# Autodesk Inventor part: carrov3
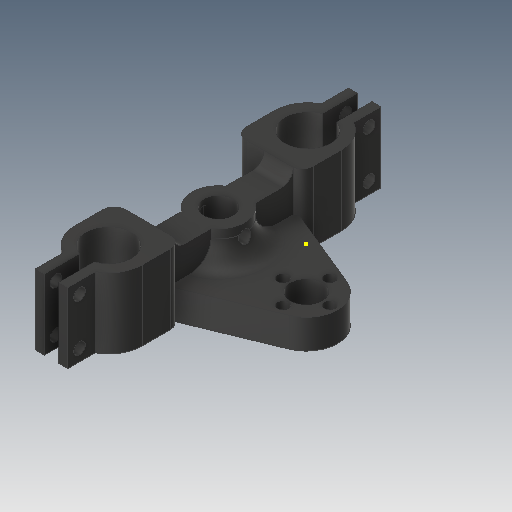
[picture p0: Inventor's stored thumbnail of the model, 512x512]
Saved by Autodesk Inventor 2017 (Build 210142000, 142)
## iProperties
Created: 2018-08
Part Number: carrov3
Material: Plastic, Opaque Black
Document SubType Name: Modeling
Designer: JK
Density: 0.952 g/cm^3
Appearance: Smooth - Black
Author: JK
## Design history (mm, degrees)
sketch "Sketch1"
  geometry: C1 r 5.5 at (0, 0); C2 r 10.671 at (0, 0); C3 r 2 at (8, 0); C4 r 2 at (0, 8); C5 r 2 at (-8, 0); C6 r 2 at (0, -8); 1 further point
  constraints: 6 centre point, 3 equal radius, 2 coincident, 2 horizontal alignment, 2 vertical alignment
  dimensions: "d0" = 11 diameter of C1; "d1" = 4 diameter of C3; "d2" = 8 distance of point (0, 0) C4.centre; "d3" = 8 distance of point (0, 0) C3.centre; "d4" = 8 distance of point (0, 0) C6.centre; "d5" = 8 distance of point (0, 0) C5.centre
extrude "Extrusion1" new body sketch "Sketch1" distance "d6" = 10; taper "d7" = 0 deg
sketch "Sketch2"
  geometry: L1 (4.051, -9.873)-(-45, -30); L2 (-45, -30)-(-45, 30); L3 (-45, 30)-(4.051, 9.873); C1 r 10.671 at (0, 0) reference; C2 r 5.3 at (0, 0); A1 r 10.671 centre (0, 0) between (4.051, -9.873) and (4.051, 9.873) reference; A2 r 10.671 centre (0, 0) between (4.051, 9.873) and (4.051, -9.873); 1 further point
  constraints: 6 end point, 4 point on circle, 2 centre point, 2 concentric, 1 coincident, 1 equal length, 1 tangent, 1 vertical, 1 vertical alignment
  dimensions: "d8" = 45 distance from line of L2 point (0, 0); "d9" = 60 distance of L1.end L2.end
extrude "Extrusion4" join sketch "Sketch2" distance "d20" = 10; taper "d21" = 0 deg
sketch "Sketch5"
  geometry: L1 (-45, 30)-(-45, -30) reference; C1 r 9 at (-30, 0); C2 r 5 at (-30, 0); 1 further point
  constraints: 2 centre point, 1 coincident
  dimensions: "d22" = 18 diameter of C1; "d23" = 10 diameter of C2; "d24" = 15 distance from line of L1 C2.centre
extrude "Extrusion5" join sketch "Sketch5" distance "d25" = 10; taper "d26" = 0 deg
fillet "Fillet1" dims "d27" = 7
fillet "Fillet2" dims "d28" = 3
sketch "Sketch6"
  geometry: L1 (34.526, 10)-(16.526, 10) reference; C1 r 2 at (25.526, 6); 1 further point
  constraints: 1 centre point
  dimensions: "d29" = 4 diameter of C1; "d30" = 4 distance from line of L1 C1.centre; "d33" = 0 horizontal distance of point (25.526, -10) C1.centre
extrude "Extrusion6" cut sketch "Sketch6" distance "d31" = 27.75; taper "d32" = 0 deg
sketch "Sketch7"
  geometry: L1 (-45, -25.526)-(-45, 25.526) reference; L2 (-45, -20.562)-(-22, -20.562); L3 (-22, -20.562)-(-22, -54.562); L4 (-22, -54.562)-(-45, -54.562); L5 (-45, -54.562)-(-45, -20.562); L6 (-45, 25.526)-(-45, -25.526) reference; L7 (-40.861, -28.302)-(4.051, -9.873) reference; C1 r 7.85 at (-33.5, -34); C2 r 5 at (-30, 0) reference; C3 r 5 at (-30, 0); 1 further point
  constraints: 8 end point, 2 centre point, 2 parallel, 2 point on line, 1 coincident, 1 collinear, 1 horizontal, 1 perpendicular
  dimensions: "d34" = 15.7 diameter of C1; "d35" = 34 vertical distance of C1.centre C3.centre; "d36" = 3.5 horizontal distance of C1.centre C3.centre; "d37" = 23 distance of L2.start L2.end; "d38" = 34 distance of L4.end L2.start
extrude "Extrusion7" join sketch "Sketch7" distance "d39" = 14; taper "d41" = 0 deg; dims "d40" = 10, "d42" = 0
sketch "Sketch8"
  geometry: L1 (-45, -54.562)-(-45, 25.526) reference; L2 (-45, -34)-(-54.023, -50.213); L3 (-54.023, -50.213)-(-46.048, -57.013); L4 (-46.048, -57.013)-(-27.663, -59.112); L5 (-27.663, -59.112)-(-16.582, -58.062); L6 (-16.582, -58.062)-(-14.815, -42.584); L7 (-14.815, -42.584)-(-18.802, -34.618); L8 (-18.802, -34.618)-(-22, -34); L9 (-22, -20.562)-(-22, -54.562) reference; C1 r 7.85 at (-33.5, -34) reference; A1 r 11.5 centre (-33.5, -34) between (-45, -34) and (-22, -34); 1 further point
  constraints: 14 end point, 2 point on circle, 2 point on line, 1 centre point, 1 concentric, 1 perpendicular
  dimensions: "d43" = 23 diameter of A1
extrude "Extrusion8" cut sketch "Sketch8" stored distance "d44" = 10; taper "d45" = 0 deg
sketch "Sketch9"
  geometry: 1 further point
sketch "Sketch10"
  geometry: L1 (-36, -51.276)-(-31, -51.276); L2 (-31, -51.276)-(-31, -36.843); L3 (-31, -36.843)-(-36, -36.843); L4 (-36, -36.843)-(-36, -51.276); L5 (-22, -34)-(-22, -20.562) reference; L6 (-45, -20.562)-(-45, -34) reference; 3 further points
  constraints: 8 end point, 2 parallel, 1 horizontal, 1 perpendicular
  dimensions: "d47" = 9 distance between parallel lines of L2 L5; "d48" = 9 distance between parallel lines of L6 L4
extrude "Extrusion9" cut sketch "Sketch10" distance "d49" = 31.5; taper "d50" = 0 deg
sketch "Sketch11"
  geometry: L1 (-36, -41.441)-(-36, -45.225) reference; L2 (-36, -41.441)-(-39, -41.441); L3 (-39, -41.441)-(-39, -53.441); L4 (-39, -53.441)-(-36, -53.441); L5 (-36, -53.441)-(-36, -41.441); L6 (-31, -45.225)-(-31, -41.441) reference; L7 (-31, -41.441)-(-28, -41.441); L8 (-28, -41.441)-(-28, -53.441); L9 (-28, -53.441)-(-31, -53.441); L10 (-31, -53.441)-(-31, -41.441); 1 further point
  constraints: 16 end point, 4 parallel, 2 collinear, 2 horizontal, 2 perpendicular
  dimensions: "d51" = 3 distance of L3.end L4.end; "d52" = 12 distance between parallel lines of L2 L4
extrude "Extrusion10" join sketch "Sketch11" distance "d53" = 24; taper "d54" = 0 deg
sketch "Sketch12"
  geometry: L1 (9.342, -24)-(0, -24) reference; L2 (0, 0)-(9.342, 0) reference; L3 (9.342, 0)-(9.342, -24) reference; C1 r 2 at (5.342, -20); C2 r 2 at (5.342, -4); 1 further point
  constraints: 2 centre point
  dimensions: "d55" = 4 diameter of C1; "d56" = 4 diameter of C2; "d57" = 4 distance from line of L1 C1.centre; "d58" = 4 distance from line of L2 C2.centre; "d61" = 4 distance from line of L3 C1.centre; "d62" = 4 distance from line of L3 C2.centre
extrude "Extrusion11" cut sketch "Sketch12" distance "d59" = 24; taper "d60" = 0 deg
mirror "Mirror1"
sketch "Sketch13"
  geometry: L1 (-35, 0)-(-25, 0); L2 (-25, 0)-(-25, -20.562); L3 (-25, -20.562)-(-35, -20.562); L4 (-35, -20.562)-(-35, 0); L5 (-22, -20.562)-(-45, -20.562) reference; L6 (-22, 20.562)-(-45, 20.562) reference; L7 (-35, 0)-(-25, 0); L8 (-25, 0)-(-25, 20.562); L9 (-25, 20.562)-(-35, 20.562); L10 (-35, 20.562)-(-35, 0); 3 further points
  constraints: 16 end point, 4 parallel, 2 horizontal, 2 horizontal alignment, 2 perpendicular, 1 collinear, 1 point on line, 2 other
extrude "Extrusion12" join sketch "Sketch13" stored distance "d63" = 24; taper "d64" = 0 deg
sketch "Sketch14"
  geometry: C1 r 5 at (-30, 0); A1 r 9 centre (-30, 0) between (-35, 7.483) and (-35, -7.483) reference; 1 further point
  constraints: 1 centre point, 1 concentric
  dimensions: "d65" = 10 diameter of C1
extrude "Extrusion13" cut sketch "Sketch14" distance "d66" = 58.25; taper "d67" = 0 deg
fillet "Fillet4" dims "d68" = 4
body "Solid1"
